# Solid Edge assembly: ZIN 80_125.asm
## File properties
Title: Zylinder
Author: bmolnar
Template: iso metric assembly.asm
Last saved by: bmolnar
Revision: 24
Application: Solid Edge
Username: bmolnar
Dokumentum tartalom típus: 1
Document Number: ZIN 80/125
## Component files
Kit_1.par
Kit_2.par
Kolbenstange.par
Profilrohr.par
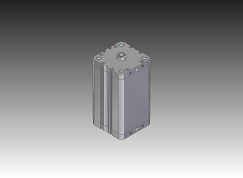
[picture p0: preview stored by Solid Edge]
